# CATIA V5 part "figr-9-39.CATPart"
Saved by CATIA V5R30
Part number: Part1
Bounding box of the stored display mesh (mm): x -40 to 40, y -20 to 191.034, z 0 to 131.022
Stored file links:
  D:\PROJECTS\CATIA V56R 2020\Resources\Parts File\c09_catia_v5_6r2020_prt\figr-9-39.CATPart
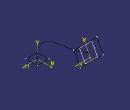
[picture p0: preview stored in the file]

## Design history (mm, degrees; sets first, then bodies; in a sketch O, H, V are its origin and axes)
Set1
  Plane1: type Normal, Curve Sketch2, RefPoint vertex of Sketch2
Body1 (main body)
  Sketch1 on xy-plane, origin (0, 0, 0), H (1, 0, 0), V (0, 1, 0)
    line L1 (20, 20) -> (20, -20)
    line L2 (20, -20) -> (-20, -20)
    line L3 (-20, -20) -> (-20, 20)
    line L4 (-20, 20) -> (20, 20)
    vertical: L1 V, L3 V
    horizontal: L2 H, L4 H
    equidistance: L1 L3 O, L2 L4 O
  Sketch2 on yz-plane, origin (0, 0, 0), H (0, 1, 0), V (0, 0, 1)
    spline S1 through (0, 0) (20, 60) (60, 80) (120, 90) (180, 110)
    point P1 (0, 0)
    coincidence: P1 O
  Sketch3 on Plane1, origin (0, 186.3865, 97.8327), H (1, 0, 0), V (0, -0.4648, 0.8854)
    point P1 (0, 13.7415)
    line L1 (40, 37.4831) -> (40, -10)
    line L2 (40, -10) -> (-40, -10)
    line L3 (-40, -10) -> (-40, 37.4831)
    line L4 (-40, 37.4831) -> (40, 37.4831)
    reference projected point E1 (0, 13.7415) from vertex of Sketch2
    coincidence: P1 V, P1 E1
    vertical: L1 V, L3 V
    horizontal: L2 H, L4 H
    equidistance: L1 L3 P1, L2 L4 P1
